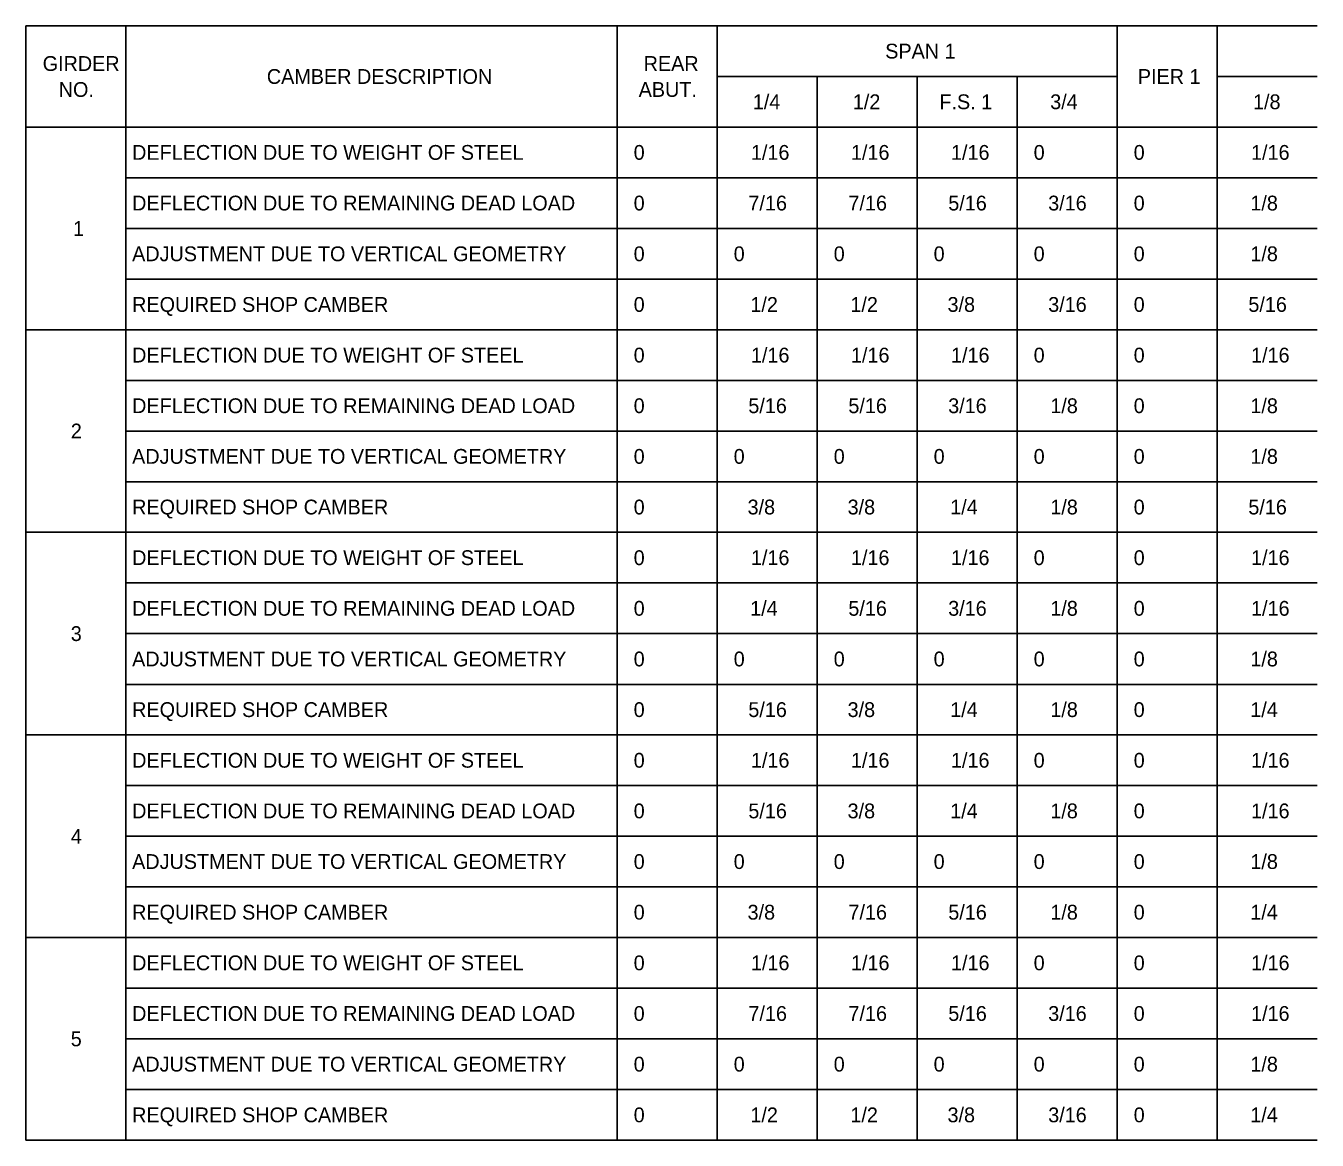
# Model space of a CAD drawing. Extents: x 2.4 to 33.4, y 1.1 to 16.7.
# Drawn here: x 2.43 to 15.87, y 1.61 to 13.21 of the extents above; entities that cross this region are included whole.
import ezdxf

# ---------------------------------------------------------------- set-up
doc = ezdxf.new("R2010")
doc.units = 0
doc.layers.add('BR_X_Slab_Object', color=7, linetype='Continuous')
doc.layers.add('SH_Border', color=7, linetype='Continuous')

msp = doc.modelspace()

# ---------------------------------------------------------------- linework, layer by layer
at = {"layer": 'BR_X_Slab_Object'}
for p, q in [((2.432, 13.205), (4.751, 13.205)), ((2.432, 13.205), (2.432, 1.61)), ((3.473, 13.205), (3.473, 1.61)), ((4.751, 13.205), (9.626, 13.205)), ((8.585, 13.205), (8.585, 1.61)), ((9.626, 13.205), (11.708, 13.205)), ((9.626, 13.205), (9.626, 1.61)), ((11.708, 13.205), (13.79, 13.205)), ((13.79, 13.205), (15.872, 13.205)), ((13.79, 13.205), (13.79, 1.61)), ((14.831, 13.205), (14.831, 1.61)), ((9.626, 12.678), (11.708, 12.678)), ((10.667, 12.678), (10.667, 1.61)), ((11.708, 12.678), (13.79, 12.678)), ((11.708, 12.678), (11.708, 1.61)), ((12.749, 12.678), (12.749, 1.61)), ((14.831, 12.678), (15.872, 12.678)), ((2.432, 12.151), (4.751, 12.151)), ((4.751, 12.151), (9.626, 12.151)), ((9.626, 12.151), (11.708, 12.151)), ((11.708, 12.151), (13.79, 12.151)), ((13.79, 12.151), (15.872, 12.151)), ((3.473, 11.624), (4.751, 11.624)), ((4.751, 11.624), (9.626, 11.624)), ((9.626, 11.624), (11.708, 11.624)), ((11.708, 11.624), (13.79, 11.624)), ((13.79, 11.624), (15.872, 11.624)), ((3.473, 11.097), (4.751, 11.097)), ((4.751, 11.097), (9.626, 11.097)), ((9.626, 11.097), (11.708, 11.097)), ((11.708, 11.097), (13.79, 11.097)), ((13.79, 11.097), (15.872, 11.097)), ((3.473, 10.57), (4.751, 10.57)), ((4.751, 10.57), (9.626, 10.57)), ((9.626, 10.57), (11.708, 10.57)), ((11.708, 10.57), (13.79, 10.57)), ((13.79, 10.57), (15.872, 10.57)), ((2.432, 10.043), (4.751, 10.043)), ((4.751, 10.043), (9.626, 10.043)), ((9.626, 10.043), (11.708, 10.043)), ((11.708, 10.043), (13.79, 10.043)), ((13.79, 10.043), (15.872, 10.043)), ((3.473, 9.516), (4.751, 9.516)), ((4.751, 9.516), (9.626, 9.516)), ((9.626, 9.516), (11.708, 9.516)), ((11.708, 9.516), (13.79, 9.516)), ((13.79, 9.516), (15.872, 9.516)), ((3.473, 8.989), (4.751, 8.989)), ((4.751, 8.989), (9.626, 8.989)), ((9.626, 8.989), (11.708, 8.989)), ((11.708, 8.989), (13.79, 8.989)), ((13.79, 8.989), (15.872, 8.989)), ((3.473, 8.462), (4.751, 8.462)), ((4.751, 8.462), (9.626, 8.462)), ((9.626, 8.462), (11.708, 8.462)), ((11.708, 8.462), (13.79, 8.462)), ((13.79, 8.462), (15.872, 8.462)), ((2.432, 7.935), (4.751, 7.935)), ((4.751, 7.935), (9.626, 7.935)), ((9.626, 7.935), (11.708, 7.935)), ((11.708, 7.935), (13.79, 7.935)), ((13.79, 7.935), (15.872, 7.935)), ((3.473, 7.408), (4.751, 7.408)), ((4.751, 7.408), (9.626, 7.408)), ((9.626, 7.408), (11.708, 7.408)), ((11.708, 7.408), (13.79, 7.408)), ((13.79, 7.408), (15.872, 7.408)), ((3.473, 6.881), (4.751, 6.881)), ((4.751, 6.881), (9.626, 6.881)), ((9.626, 6.881), (11.708, 6.881)), ((11.708, 6.881), (13.79, 6.881)), ((13.79, 6.881), (15.872, 6.881)), ((3.473, 6.353), (4.751, 6.353)), ((4.751, 6.353), (9.626, 6.353)), ((9.626, 6.353), (11.708, 6.353)), ((11.708, 6.353), (13.79, 6.353)), ((13.79, 6.353), (15.872, 6.353)), ((2.432, 5.826), (4.751, 5.826)), ((4.751, 5.826), (9.626, 5.826)), ((9.626, 5.826), (11.708, 5.826)), ((11.708, 5.826), (13.79, 5.826)), ((13.79, 5.826), (15.872, 5.826)), ((3.473, 5.299), (4.751, 5.299)), ((4.751, 5.299), (9.626, 5.299)), ((9.626, 5.299), (11.708, 5.299)), ((11.708, 5.299), (13.79, 5.299)), ((13.79, 5.299), (15.872, 5.299)), ((3.473, 4.772), (4.751, 4.772)), ((4.751, 4.772), (9.626, 4.772)), ((9.626, 4.772), (11.708, 4.772)), ((11.708, 4.772), (13.79, 4.772)), ((13.79, 4.772), (15.872, 4.772)), ((3.473, 4.245), (4.751, 4.245)), ((4.751, 4.245), (9.626, 4.245)), ((9.626, 4.245), (11.708, 4.245)), ((11.708, 4.245), (13.79, 4.245)), ((13.79, 4.245), (15.872, 4.245)), ((2.432, 3.718), (4.751, 3.718)), ((4.751, 3.718), (9.626, 3.718)), ((9.626, 3.718), (11.708, 3.718)), ((11.708, 3.718), (13.79, 3.718)), ((13.79, 3.718), (15.872, 3.718)), ((3.473, 3.191), (4.751, 3.191)), ((4.751, 3.191), (9.626, 3.191)), ((9.626, 3.191), (11.708, 3.191)), ((11.708, 3.191), (13.79, 3.191)), ((13.79, 3.191), (15.872, 3.191)), ((3.473, 2.664), (4.751, 2.664)), ((4.751, 2.664), (9.626, 2.664)), ((9.626, 2.664), (11.708, 2.664)), ((11.708, 2.664), (13.79, 2.664)), ((13.79, 2.664), (15.872, 2.664)), ((3.473, 2.137), (4.751, 2.137)), ((4.751, 2.137), (9.626, 2.137)), ((9.626, 2.137), (11.708, 2.137)), ((11.708, 2.137), (13.79, 2.137)), ((13.79, 2.137), (15.872, 2.137)), ((2.432, 1.61), (4.751, 1.61)), ((4.751, 1.61), (9.626, 1.61)), ((9.626, 1.61), (11.708, 1.61)), ((11.708, 1.61), (13.79, 1.61)), ((13.79, 1.61), (15.872, 1.61))]:
    msp.add_line(p, q, dxfattribs=at)

# ---------------------------------------------------------------- texts
at = {"layer": 'SH_Border'}
for s, p in [('SPAN 1', (11.376, 12.865)), ('GIRDER', (2.607, 12.736)), ('REAR', (8.862, 12.736)), ('CAMBER DESCRIPTION', (4.94, 12.601)), ('PIER 1', (14.005, 12.601)), ('NO.', (2.774, 12.466)), ('ABUT.', (8.81, 12.466)), ('1/4', (9.998, 12.338)), ('1/2', (11.039, 12.338)), ('3/4', (13.093, 12.338)), ('1/8', (15.204, 12.338)), ('F.S. 1', (11.94, 12.338)), ('DEFLECTION DUE TO WEIGHT OF STEEL', (3.538, 11.811)), ('0      ', (8.758, 11.811)), ('  1/16', (9.864, 11.811)), ('  1/16', (10.905, 11.811)), ('  1/16', (11.946, 11.811)), ('0      ', (12.921, 11.811)), ('0      ', (13.962, 11.811)), ('  1/16', (15.069, 11.811)), ('DEFLECTION DUE TO REMAINING DEAD LOAD', (3.538, 11.284)), ('0      ', (8.758, 11.284)), ('  7/16', (9.838, 11.284)), ('  7/16', (10.879, 11.284)), ('  5/16', (11.918, 11.284)), ('  3/16', (12.958, 11.284)), ('0      ', (13.962, 11.284)), ('  1/8 ', (15.062, 11.284)), ('1', (2.923, 11.02)), ('ADJUSTMENT DUE TO VERTICAL GEOMETRY', (3.538, 10.756)), ('0      ', (8.758, 10.756)), ('0      ', (9.799, 10.756)), ('0      ', (10.84, 10.756)), ('0      ', (11.88, 10.756)), ('0      ', (12.921, 10.756)), ('0      ', (13.962, 10.756)), ('  1/8 ', (15.062, 10.756)), ('REQUIRED SHOP CAMBER', (3.538, 10.229)), ('0      ', (8.758, 10.229)), ('  1/2 ', (9.858, 10.229)), ('  1/2 ', (10.899, 10.229)), ('  3/8 ', (11.91, 10.229)), ('  3/16', (12.958, 10.229)), ('0      ', (13.962, 10.229)), ('  5/16', (15.041, 10.229)), ('DEFLECTION DUE TO WEIGHT OF STEEL', (3.538, 9.702)), ('0      ', (8.758, 9.702)), ('  1/16', (9.864, 9.702)), ('  1/16', (10.905, 9.702)), ('  1/16', (11.946, 9.702)), ('0      ', (12.921, 9.702)), ('0      ', (13.962, 9.702)), ('  1/16', (15.069, 9.702)), ('DEFLECTION DUE TO REMAINING DEAD LOAD', (3.538, 9.175)), ('0      ', (8.758, 9.175)), ('  5/16', (9.837, 9.175)), ('  5/16', (10.878, 9.175)), ('  3/16', (11.917, 9.175)), ('  1/8 ', (12.98, 9.175)), ('0      ', (13.962, 9.175)), ('  1/8 ', (15.062, 9.175)), ('2', (2.9, 8.912)), ('ADJUSTMENT DUE TO VERTICAL GEOMETRY', (3.538, 8.648)), ('0      ', (8.758, 8.648)), ('0      ', (9.799, 8.648)), ('0      ', (10.84, 8.648)), ('0      ', (11.88, 8.648)), ('0      ', (12.921, 8.648)), ('0      ', (13.962, 8.648)), ('  1/8 ', (15.062, 8.648)), ('REQUIRED SHOP CAMBER', (3.538, 8.121)), ('0      ', (8.758, 8.121)), ('  3/8 ', (9.829, 8.121)), ('  3/8 ', (10.87, 8.121)), ('  1/4 ', (11.938, 8.121)), ('  1/8 ', (12.98, 8.121)), ('0      ', (13.962, 8.121)), ('  5/16', (15.041, 8.121)), ('DEFLECTION DUE TO WEIGHT OF STEEL', (3.538, 7.594)), ('0      ', (8.758, 7.594)), ('  1/16', (9.864, 7.594)), ('  1/16', (10.905, 7.594)), ('  1/16', (11.946, 7.594)), ('0      ', (12.921, 7.594)), ('0      ', (13.962, 7.594)), ('  1/16', (15.069, 7.594)), ('DEFLECTION DUE TO REMAINING DEAD LOAD', (3.538, 7.067)), ('0      ', (8.758, 7.067)), ('  1/4 ', (9.856, 7.067)), ('  5/16', (10.878, 7.067)), ('  3/16', (11.917, 7.067)), ('  1/8 ', (12.98, 7.067)), ('0      ', (13.962, 7.067)), ('  1/16', (15.069, 7.067)), ('3', (2.899, 6.804)), ('ADJUSTMENT DUE TO VERTICAL GEOMETRY', (3.538, 6.54)), ('0      ', (8.758, 6.54)), ('0      ', (9.799, 6.54)), ('0      ', (10.84, 6.54)), ('0      ', (11.88, 6.54)), ('0      ', (12.921, 6.54)), ('0      ', (13.962, 6.54)), ('  1/8 ', (15.062, 6.54)), ('REQUIRED SHOP CAMBER', (3.538, 6.013)), ('0      ', (8.758, 6.013)), ('  5/16', (9.837, 6.013)), ('  3/8 ', (10.87, 6.013)), ('  1/4 ', (11.938, 6.013)), ('  1/8 ', (12.98, 6.013)), ('0      ', (13.962, 6.013)), ('  1/4 ', (15.061, 6.013)), ('  1/16', (9.864, 5.486)), ('  1/16', (10.905, 5.486)), ('  1/16', (11.946, 5.486)), ('  1/16', (15.069, 5.486)), ('DEFLECTION DUE TO WEIGHT OF STEEL', (3.538, 5.486)), ('0      ', (8.758, 5.486)), ('0      ', (12.921, 5.486)), ('0      ', (13.962, 5.486)), ('DEFLECTION DUE TO REMAINING DEAD LOAD', (3.538, 4.959)), ('0      ', (8.758, 4.959)), ('  5/16', (9.837, 4.959)), ('  3/8 ', (10.87, 4.959)), ('  1/4 ', (11.938, 4.959)), ('  1/8 ', (12.98, 4.959)), ('0      ', (13.962, 4.959)), ('  1/16', (15.069, 4.959)), ('4', (2.901, 4.695)), ('ADJUSTMENT DUE TO VERTICAL GEOMETRY', (3.538, 4.432)), ('0      ', (8.758, 4.432)), ('0      ', (9.799, 4.432)), ('0      ', (10.84, 4.432)), ('0      ', (11.88, 4.432)), ('0      ', (12.921, 4.432)), ('0      ', (13.962, 4.432)), ('  1/8 ', (15.062, 4.432)), ('REQUIRED SHOP CAMBER', (3.538, 3.905)), ('0      ', (8.758, 3.905)), ('  3/8 ', (9.829, 3.905)), ('  7/16', (10.879, 3.905)), ('  5/16', (11.918, 3.905)), ('  1/8 ', (12.98, 3.905)), ('0      ', (13.962, 3.905)), ('  1/4 ', (15.061, 3.905)), ('DEFLECTION DUE TO WEIGHT OF STEEL', (3.538, 3.378)), ('0      ', (8.758, 3.378)), ('  1/16', (9.864, 3.378)), ('  1/16', (10.905, 3.378)), ('  1/16', (11.946, 3.378)), ('0      ', (12.921, 3.378)), ('0      ', (13.962, 3.378)), ('  1/16', (15.069, 3.378)), ('DEFLECTION DUE TO REMAINING DEAD LOAD', (3.538, 2.851)), ('0      ', (8.758, 2.851)), ('  7/16', (9.838, 2.851)), ('  7/16', (10.879, 2.851)), ('  5/16', (11.918, 2.851)), ('  3/16', (12.958, 2.851)), ('0      ', (13.962, 2.851)), ('  1/16', (15.069, 2.851)), ('5', (2.899, 2.587)), ('ADJUSTMENT DUE TO VERTICAL GEOMETRY', (3.538, 2.324)), ('0      ', (8.758, 2.324)), ('0      ', (9.799, 2.324)), ('0      ', (10.84, 2.324)), ('0      ', (11.88, 2.324)), ('0      ', (12.921, 2.324)), ('0      ', (13.962, 2.324)), ('  1/8 ', (15.062, 2.324)), ('REQUIRED SHOP CAMBER', (3.538, 1.796)), ('0      ', (8.758, 1.796)), ('  1/2 ', (9.858, 1.796)), ('  1/2 ', (10.899, 1.796)), ('  3/8 ', (11.91, 1.796)), ('  3/16', (12.958, 1.796)), ('0      ', (13.962, 1.796)), ('  1/4 ', (15.061, 1.796))]:
    msp.add_text(s, height=0.154, dxfattribs=at).set_placement(p)

doc.saveas('drawing.dxf')
